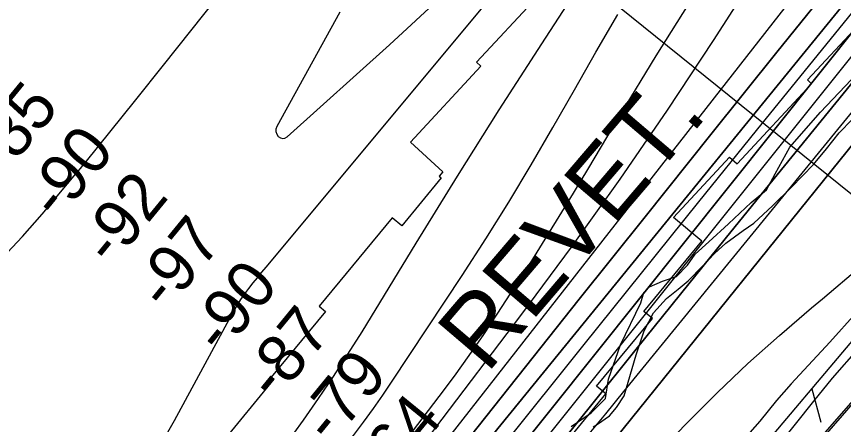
# Model space of a CAD drawing. Extents: x 3598634 to 3636690, y 517270 to 542944.
# Drawn here: x 3606411 to 3607580, y 527991 to 528569 of the extents above; entities that cross this region are included whole.
import ezdxf

# ---------------------------------------------------------------- set-up
doc = ezdxf.new("R2010")
doc.units = 0
for name, color, linetype in [('V-FLOD-BASE', 7, 'Continuous'), ('V-LEVE-TOET', 7, 'Continuous'), ('V-RIVR-EDGE', 7, 'Continuous'), ('V-RIVR-RANG', 7, 'Continuous'), ('V-RRAP-FSHR', 7, 'Continuous'), ('V-RRAP-RVMT', 7, 'Continuous'), ('V-RRAP-RVMT-IDEN', 7, 'Continuous'), ('V-SITE-VEGE', 7, 'Continuous'), ('V-SURV-LINE', 7, 'Continuous'), ('V-TOPO-DPTH', 7, 'Continuous'), ('V-TOPO-MAJR', 7, 'Continuous'), ('V-TOPO-MINR', 7, 'Continuous'), ('V-TOPO-WATR', 7, 'Continuous')]:
    doc.layers.add(name, color=color, linetype=linetype)

msp = doc.modelspace()

# ---------------------------------------------------------------- linework, layer by layer
at = {"layer": 'V-FLOD-BASE'}
msp.add_lwpolyline([(3606855.7, 527176), (3606941.6, 527272.6), (3607017.1, 527362.2), (3607123.3, 527485.2), (3607190.4, 527557.4), (3607286.8, 527667.9), (3607388.8, 527786.7), (3607446.1, 527850.6), (3607578.9, 528003.5), (3607669.7, 528108.4), (3607782.2, 528239), (3607843.7, 528310.5), (3607962.5, 528439.8), (3608057.5, 528550.9), (3608164.4, 528673.2)], dxfattribs=at)
at = {"layer": 'V-LEVE-TOET'}
msp.add_lwpolyline([(3607601.5, 528098.8), (3607564.4, 528056.4), (3607537.9, 528023.8), (3607488.2, 527961.2), (3607419.1, 527881.3), (3607381.3, 527839), (3607353.4, 527805.6), (3607326.1, 527776.4), (3607292.6, 527739.6), (3607250.6, 527684.7), (3607177.3, 527602), (3607062, 527470.7), (3606981.7, 527383.2), (3606929.9, 527320), (3606868.4, 527249.1), (3606793, 527162.3)], dxfattribs=at)
at = {"layer": 'V-RIVR-EDGE'}
msp.add_lwpolyline([(3607195.5, 527988.1), (3607223.8, 528007.2), (3607243.7, 528027.6), (3607247.9, 528055.2), (3607264.9, 528103.7), (3607293.8, 528163.1), (3607298.1, 528177.5), (3607305.9, 528185.9), (3607324.5, 528193.7), (3607344.3, 528200.2), (3607360, 528216.4), (3607370.8, 528232), (3607390.1, 528249.3), (3607417.8, 528275.1), (3607449.7, 528305), (3607471.3, 528323), (3607484, 528345.7), (3607504.5, 528383.5), (3607547.8, 528433.2), (3607600.2, 528488.3)], dxfattribs=at)
at = {"layer": 'V-RIVR-RANG'}
msp.add_line((3607752.6, 528186.5), (3607037.5, 528765.2), dxfattribs=at)
at = {"layer": 'V-RRAP-FSHR'}
msp.add_line((3607535.7, 528041.1), (3607548.3, 527993.9), dxfattribs=at)
for points in [[(3605375.2, 525433.8), (3605456, 525580.5), (3605630.7, 525877.6), (3605746.8, 526080.3), (3605800.6, 526159), (3605867.3, 526231.6), (3605948.4, 526309.6), (3606191.9, 526556.5), (3606564.8, 526949.6), (3606877.9, 527278.9), (3607054.8, 527479.5), (3607380.2, 527856.8), (3607669.2, 528199.4), (3608066.5, 528645), (3608475.6, 529114.7), (3608696.8, 529377), (3608831.9, 529536), (3608922.8, 529648.8), (3609014.7, 529727.8), (3609124.2, 529832), (3609276.1, 529976.3)], [(3607360.2, 527833.6), (3607380.2, 527856.8), (3607669.2, 528199.4), (3607973.9, 528541.1)]]:
    msp.add_lwpolyline(points, dxfattribs=at)
at = {"layer": 'V-RRAP-RVMT'}
for p, q in [((3607166.6, 528617.3), (3607061.3, 528503.7)), ((3607529.4, 528478.8), (3607630.3, 528587.7)), ((3607067.4, 528498.1), (3606968, 528390.8)), ((3607061.3, 528503.7), (3607067.4, 528498.1)), ((3607430, 528359.7), (3607535.2, 528473.4)), ((3607535.2, 528473.4), (3607529.4, 528478.8)), ((3606968, 528390.8), (3607013.7, 528348.5)), ((3607339.9, 528283.9), (3607419.3, 528369.6)), ((3607419.3, 528369.6), (3607430, 528359.7)), ((3607013.7, 528348.5), (3607008.8, 528342.5)), ((3607008.8, 528342.5), (3607011.7, 528340)), ((3607011.7, 528340), (3606955.7, 528271.9)), ((3607380.3, 528250.6), (3607339.9, 528283.9)), ((3606942, 528283.4), (3606838.9, 528158.2)), ((3606955.7, 528271.9), (3606942, 528283.4)), ((3607298.3, 528150.9), (3607380.3, 528250.6)), ((3606838.9, 528158.2), (3606847.8, 528150.9)), ((3606847.8, 528150.9), (3606771, 528057.9)), ((3607310.2, 528141.1), (3607298.3, 528150.9)), ((3607231.3, 528045.2), (3607310.2, 528141.1)), ((3606774.7, 528054.9), (3606690.9, 527952.6)), ((3606771, 528057.9), (3606774.7, 528054.9)), ((3607244.4, 528034.4), (3607231.3, 528045.2)), ((3607167.8, 527941.3), (3607244.4, 528034.4))]:
    msp.add_line(p, q, dxfattribs=at)
at = {"layer": 'V-SITE-VEGE'}
for points in [[(3607226.4, 527987.7), (3607232.7, 527991.2), (3607249.5, 528003), (3607259.2, 528014.8), (3607270.4, 528031.5), (3607287.3, 528089.3), (3607298.6, 528123.4), (3607311.9, 528149.1), (3607330, 528169.2), (3607346.8, 528182.4), (3607360.7, 528194.2), (3607381.7, 528215.7), (3607397.8, 528233.1), (3607413.8, 528247.7), (3607438.3, 528265.7), (3607453.6, 528276.1), (3607480.1, 528300.4), (3607506.7, 528326.8), (3607538.1, 528358.8), (3607556.3, 528381), (3607574.5, 528403.9), (3607592.6, 528422.7)], [(3607598.1, 528149), (3607561.1, 528107.3), (3607506.6, 528048.2), (3607485.6, 528024.6), (3607461.9, 527995.4), (3607437.4, 527967.6)]]:
    msp.add_lwpolyline(points, dxfattribs=at)
at = {"layer": 'V-SURV-LINE'}
msp.add_lwpolyline([(3606955.7, 527293.4), (3607820.1, 528283.5)], dxfattribs=at)
at = {"layer": 'V-TOPO-DPTH'}
for points in [[(3606235.2, 526930.9), (3606440.2, 527167.6), (3606463.9, 527195.4), (3606487.4, 527223.4), (3606510.5, 527251.7), (3606533.4, 527280.2), (3607009.7, 527882.8), (3607014, 527888.2), (3607018.2, 527893.6), (3607022.4, 527899), (3607026.7, 527904.4), (3607030.2, 527908.9), (3607032.6, 527912.1), (3607035.1, 527915.2), (3607037.6, 527918.3), (3607040.1, 527921.5), (3607042.6, 527924.6), (3607045.1, 527927.7), (3607047.6, 527930.8), (3607050.1, 527933.9), (3607754.7, 528800.4)], [(3607754.7, 528800.4), (3607050.1, 527933.9), (3607047.6, 527930.8), (3607045.1, 527927.7), (3607042.6, 527924.6), (3607040.1, 527921.5), (3607037.6, 527918.3), (3607035.1, 527915.2), (3607032.6, 527912.1), (3607030.2, 527908.9), (3607026.7, 527904.4), (3607022.4, 527899), (3607018.2, 527893.6), (3607014, 527888.2), (3607009.7, 527882.8), (3606533.4, 527280.2), (3606510.5, 527251.7), (3606487.4, 527223.4), (3606463.9, 527195.4), (3606440.2, 527167.6), (3606235.2, 526930.9)], [(3607814.4, 528747.3), (3607476.4, 528331.4), (3607413.2, 528253.5), (3607350.1, 528175.5), (3607287.2, 528097.4), (3607224.4, 528019.3), (3607109.4, 527875.9), (3607104.1, 527869.4), (3607098.9, 527862.8), (3607093.6, 527856.2), (3607088.4, 527849.7), (3607032.3, 527779.2), (3606999, 527737.5), (3606965.8, 527695.7), (3606932.5, 527653.9), (3606899.2, 527612.2), (3606584.6, 527217.9), (3606568.4, 527197.7), (3606552.1, 527177.6), (3606535.6, 527157.7), (3606519.1, 527137.7), (3606362.9, 526951.2)], [(3606362.9, 526951.2), (3606519.1, 527137.7), (3606535.6, 527157.7), (3606552.1, 527177.6), (3606568.4, 527197.7), (3606584.6, 527217.9), (3606899.2, 527612.2), (3606932.5, 527653.9), (3606965.8, 527695.7), (3606999, 527737.5), (3607032.3, 527779.2), (3607088.4, 527849.7), (3607093.6, 527856.2), (3607098.9, 527862.8), (3607104.1, 527869.4), (3607109.4, 527875.9), (3607224.4, 528019.3), (3607287.2, 528097.4), (3607350.1, 528175.5), (3607413.2, 528253.5), (3607476.4, 528331.4), (3607814.4, 528747.3)], [(3606352.7, 527134.1), (3606433, 527226.8), (3606442.3, 527237.7), (3606451.5, 527248.7), (3606460.6, 527259.8), (3606469.6, 527270.9), (3606564.2, 527390), (3606620.4, 527460.9), (3606676.5, 527531.8), (3606732.4, 527602.8), (3606788.3, 527673.8), (3606965.9, 527900.3), (3606983, 527922.1), (3607000.1, 527944), (3607017.2, 527965.8), (3607034.2, 527987.6), (3607564, 528666.3)], [(3606352.7, 527134.1), (3606433, 527226.8), (3606442.3, 527237.7), (3606451.5, 527248.7), (3606460.6, 527259.8), (3606469.6, 527270.9), (3606564.2, 527390), (3606620.4, 527460.9), (3606676.5, 527531.8), (3606732.4, 527602.8), (3606788.3, 527673.8), (3606965.9, 527900.3), (3606983, 527922.1), (3607000.1, 527944), (3607017.2, 527965.8), (3607034.2, 527987.6), (3607564, 528666.3)], [(3606294, 527032.6), (3606436.6, 527197.3), (3606453.1, 527216.6), (3606469.4, 527236.1), (3606485.5, 527255.7), (3606501.4, 527275.5), (3606780.9, 527628.5), (3606820.5, 527678.5), (3606860.1, 527728.7), (3606899.5, 527778.9), (3606938.8, 527829.1), (3607003.9, 527912.3), (3607010.7, 527921), (3607017.5, 527929.7), (3607024.4, 527938.3), (3607031.2, 527947), (3607206.8, 528168.1), (3607299.8, 528284.9), (3607392.9, 528401.6), (3607486.3, 528518.1), (3607579.8, 528634.5)], [(3607579.8, 528634.5), (3607486.3, 528518.1), (3607392.9, 528401.6), (3607299.8, 528284.9), (3607206.8, 528168.1), (3607031.2, 527947), (3607024.4, 527938.3), (3607017.5, 527929.7), (3607010.7, 527921), (3607003.9, 527912.3), (3606938.8, 527829.1), (3606899.5, 527778.9), (3606860.1, 527728.7), (3606820.5, 527678.5), (3606780.9, 527628.5), (3606501.4, 527275.5), (3606485.5, 527255.7), (3606469.4, 527236.1), (3606453.1, 527216.6), (3606436.6, 527197.3), (3606294, 527032.6)], [(3607764.9, 528600.3), (3607732.3, 528559.8), (3607699.6, 528519.3), (3607166.6, 527857.8), (3607154.3, 527842.6), (3607141.9, 527827.4), (3607129.4, 527812.4), (3607116.9, 527797.4), (3606811.9, 527434.6), (3606773.3, 527388.5), (3606734.8, 527342.3), (3606696.5, 527295.9), (3606658.4, 527249.4), (3606638.3, 527224.8), (3606610.2, 527190.6), (3606582.1, 527156.4), (3606553.9, 527122.4), (3606525.5, 527088.4), (3606200.6, 526699.9)], [(3607641.8, 528607.4), (3607607, 528563.8), (3607103.4, 527932.6), (3607085.7, 527910.4), (3607068, 527888.2), (3607050.3, 527865.9), (3607032.7, 527843.7), (3606691, 527412), (3606662.8, 527376.5), (3606634.7, 527340.9), (3606606.5, 527305.4), (3606578.3, 527269.9), (3606531, 527210.3), (3606526.4, 527204.6), (3606521.8, 527199), (3606517.2, 527193.3), (3606512.6, 527187.7), (3606479.5, 527148.3), (3606458.2, 527123.1), (3606436.6, 527098), (3606414.8, 527073.2), (3606392.8, 527048.6)], [(3606392.8, 527048.6), (3606414.8, 527073.2), (3606436.6, 527098), (3606458.2, 527123.1), (3606479.5, 527148.3), (3606512.6, 527187.7), (3606517.2, 527193.3), (3606521.8, 527199), (3606526.4, 527204.6), (3606531, 527210.3), (3606578.3, 527269.9), (3606606.5, 527305.4), (3606634.7, 527340.9), (3606662.8, 527376.5), (3606691, 527412), (3607032.7, 527843.7), (3607050.3, 527865.9), (3607068, 527888.2), (3607085.7, 527910.4), (3607103.4, 527932.6), (3607607, 528563.8), (3607641.8, 528607.4)]]:
    msp.add_lwpolyline(points, dxfattribs=at)
at = {"layer": 'V-TOPO-MAJR'}
for points in [[(3606405.6, 527229), (3606411.1, 527235.3), (3606429.4, 527256.3), (3606431.5, 527258.8), (3606433.6, 527261.3), (3606435.6, 527263.8), (3606437.7, 527266.3), (3606459.8, 527294), (3606472.8, 527310.5), (3606485.9, 527326.9), (3606498.9, 527343.3), (3606511.9, 527359.8), (3606962.4, 527932.5), (3606972.5, 527945.4), (3606982.5, 527958.4), (3606992.5, 527971.4), (3607002.5, 527984.5), (3607125.5, 528146.9), (3607195.9, 528242), (3607264.7, 528338.1), (3607331.3, 528435.8), (3607396.5, 528534.5), (3607595.7, 528844.2)], [(3606868.3, 528574.7), (3606779.1, 528413), (3606777.9, 528409.2), (3606777.7, 528405.5), (3606778.9, 528402), (3606781, 528398.6), (3606784.2, 528396.7), (3606787.4, 528395.8), (3606790.6, 528396.5), (3606793.9, 528398.2), (3606938.5, 528528.4), (3607012.8, 528597.7)]]:
    msp.add_lwpolyline(points, dxfattribs=at)
at = {"layer": 'V-TOPO-MINR'}
for points in [[(3606390.7, 528226.3), (3606419.4, 528257.1), (3606447.3, 528288.8), (3606495, 528345.6), (3606498.3, 528349.6), (3606501.6, 528353.5), (3606504.9, 528357.5), (3606508.1, 528361.5), (3606579.8, 528450.8), (3606618.8, 528499.6), (3606657.6, 528548.4), (3606696.1, 528597.5), (3606734.6, 528646.6), (3607212.9, 529261.6), (3607227, 529280), (3607240.9, 529298.4), (3607254.6, 529317), (3607268.2, 529335.8), (3607599.5, 529800), (3607644.1, 529862.4), (3607688.7, 529924.8)], [(3608167.6, 529919.3), (3608117.8, 529858.1), (3608068, 529796.9), (3608018.1, 529735.6), (3607540, 529148.3), (3607517.1, 529120.3), (3607494.1, 529092.3), (3607471, 529064.4), (3607447.9, 529036.5), (3606763.5, 528213.8), (3606757.3, 528206.3), (3606751.2, 528198.7), (3606745.1, 528191.2), (3606739.1, 528183.5), (3606733.3, 528175.7), (3606727.8, 528167.8), (3606722.7, 528159.5), (3606717.8, 528151.1), (3606633.9, 527995.8), (3606585.3, 527910.9), (3606534, 527827.8), (3606478.6, 527747.4), (3606420.5, 527668.7), (3606248.6, 527447.8)], [(3606207.9, 526878.1), (3606462.1, 527163.5), (3606483.2, 527187.4), (3606504.1, 527211.6), (3606524.7, 527235.9), (3606545.2, 527260.4), (3606565.4, 527285.1), (3606585.6, 527309.9), (3606605.5, 527334.9), (3606625.3, 527359.9), (3607003.7, 527840.4), (3607027.7, 527870.9), (3607051.9, 527901.4), (3607076.1, 527931.8), (3607100.3, 527962.2), (3607213.7, 528103.9), (3607294.8, 528205.1), (3607376, 528306.1), (3607457.4, 528407), (3607538.9, 528507.8), (3607788.1, 528815.6)], [(3606235.2, 526930.9), (3606440.2, 527167.6), (3606463.9, 527195.4), (3606487.4, 527223.4), (3606510.5, 527251.7), (3606533.4, 527280.2), (3607009.7, 527882.8), (3607014, 527888.2), (3607018.2, 527893.6), (3607022.4, 527899), (3607026.7, 527904.4), (3607030.2, 527908.9), (3607032.6, 527912.1), (3607035.1, 527915.2), (3607037.6, 527918.3), (3607040.1, 527921.5), (3607042.6, 527924.6), (3607045.1, 527927.7), (3607047.6, 527930.8), (3607050.1, 527933.9), (3607754.7, 528800.4)], [(3606284.8, 526829.2), (3606522.3, 527112.8), (3606544.8, 527139.8), (3606567.2, 527167), (3606589.4, 527194.2), (3606611.5, 527221.6), (3607005.2, 527711.9), (3607023.5, 527734.8), (3607042, 527757.7), (3607060.4, 527780.5), (3607078.9, 527803.3), (3607097.4, 527826), (3607115.9, 527848.8), (3607134.5, 527871.5), (3607153, 527894.3), (3607167.3, 527911.7), (3607193, 527943.1), (3607218.6, 527974.5), (3607244.3, 528006), (3607269.9, 528037.4), (3607833.2, 528728.4)], [(3606352.7, 527134.1), (3606433, 527226.8), (3606442.3, 527237.7), (3606451.5, 527248.7), (3606460.6, 527259.8), (3606469.6, 527270.9), (3606564.2, 527390), (3606620.4, 527460.9), (3606676.5, 527531.8), (3606732.4, 527602.8), (3606788.3, 527673.8), (3606965.9, 527900.3), (3606983, 527922.1), (3607000.1, 527944), (3607017.2, 527965.8), (3607034.2, 527987.6), (3607564, 528666.3)], [(3606294, 527032.6), (3606436.6, 527197.3), (3606453.1, 527216.6), (3606469.4, 527236.1), (3606485.5, 527255.7), (3606501.4, 527275.5), (3606780.9, 527628.5), (3606820.5, 527678.5), (3606860.1, 527728.7), (3606899.5, 527778.9), (3606938.8, 527829.1), (3607003.9, 527912.3), (3607010.7, 527921), (3607017.5, 527929.7), (3607024.4, 527938.3), (3607031.2, 527947), (3607206.8, 528168.1), (3607299.8, 528284.9), (3607392.9, 528401.6), (3607486.3, 528518.1), (3607579.8, 528634.5)], [(3606299.3, 527384.5), (3606681.2, 527823.8), (3606712.9, 527861.3), (3606743.9, 527899.4), (3606773.9, 527938.4), (3606803.1, 527977.9), (3606816.6, 527996.8), (3606838.2, 528027.6), (3606859.2, 528058.7), (3606879.6, 528090.2), (3606899.6, 528122), (3606976.3, 528247.7), (3607034.6, 528342.3), (3607093.6, 528436.5), (3607153.6, 528530.1), (3607214.1, 528623.3)], [(3606200.6, 526699.9), (3606525.5, 527088.4), (3606553.9, 527122.4), (3606582.1, 527156.4), (3606610.2, 527190.6), (3606638.3, 527224.8), (3606658.4, 527249.4), (3606696.5, 527295.9), (3606734.8, 527342.3), (3606773.3, 527388.5), (3606811.9, 527434.6), (3607116.9, 527797.4), (3607129.4, 527812.4), (3607141.9, 527827.4), (3607154.3, 527842.6), (3607166.6, 527857.8), (3607699.6, 528519.3), (3607732.3, 528559.8), (3607764.9, 528600.3)], [(3606392.8, 527048.6), (3606414.8, 527073.2), (3606436.6, 527098), (3606458.2, 527123.1), (3606479.5, 527148.3), (3606512.6, 527187.7), (3606517.2, 527193.3), (3606521.8, 527199), (3606526.4, 527204.6), (3606531, 527210.3), (3606578.3, 527269.9), (3606606.5, 527305.4), (3606634.7, 527340.9), (3606662.8, 527376.5), (3606691, 527412), (3607032.7, 527843.7), (3607050.3, 527865.9), (3607068, 527888.2), (3607085.7, 527910.4), (3607103.4, 527932.6), (3607607, 528563.8), (3607641.8, 528607.4)], [(3606387.4, 527010.3), (3606431.6, 527062.2), (3606515.8, 527162.7), (3606526.4, 527175.5), (3606536.9, 527188.3), (3606547.4, 527201.2), (3606557.8, 527214.1), (3606667.4, 527351.9), (3606732.6, 527433.8), (3606797.7, 527515.7), (3606862.8, 527597.6), (3606927.9, 527679.5), (3607060.7, 527846.7), (3607072.1, 527861.1), (3607083.5, 527875.4), (3607094.9, 527889.8), (3607106.4, 527904.1), (3607573.8, 528489.3), (3607616.8, 528543), (3607659.9, 528596.7)], [(3606971.1, 527980.8), (3607008.6, 528030.3), (3607030.1, 528059.3), (3607051.2, 528088.6), (3607071.6, 528118.4), (3607091.6, 528148.4), (3607109, 528175.2), (3607137.1, 528219), (3607164.9, 528263), (3607192.1, 528307.4), (3607218.9, 528352.1), (3607264.9, 528429.7), (3607315.3, 528512.7), (3607366.9, 528595)], [(3606365.7, 527325.1), (3606457, 527431.8), (3606506.4, 527490.5), (3606555.3, 527549.6), (3606603.3, 527609.5), (3606650.7, 527669.8), (3606887.6, 527975.4), (3606901.8, 527994.2), (3606915.7, 528013.2), (3606929.2, 528032.5), (3606942.4, 528052.1), (3607041.2, 528202), (3607074.5, 528253.7), (3607107, 528305.7), (3607138.6, 528358.4), (3607169.4, 528411.5), (3607199.9, 528464.8), (3607230.4, 528518.2), (3607261.1, 528571.4)], [(3607328.1, 527960.8), (3607359.9, 527993.7), (3607402.1, 528035.9), (3607445.3, 528077.1), (3607489.7, 528117), (3607535.1, 528155.8), (3607550.7, 528168.7), (3607603.8, 528214.1)]]:
    msp.add_lwpolyline(points, dxfattribs=at)
at = {"layer": 'V-TOPO-WATR'}
msp.add_lwpolyline([(3606362.9, 526951.2), (3606519.1, 527137.7), (3606535.6, 527157.7), (3606552.1, 527177.6), (3606568.4, 527197.7), (3606584.6, 527217.9), (3606899.2, 527612.2), (3606932.5, 527653.9), (3606965.8, 527695.7), (3606999, 527737.5), (3607032.3, 527779.2), (3607088.4, 527849.7), (3607093.6, 527856.2), (3607098.9, 527862.8), (3607104.1, 527869.4), (3607109.4, 527875.9), (3607224.4, 528019.3), (3607287.2, 528097.4), (3607350.1, 528175.5), (3607413.2, 528253.5), (3607476.4, 528331.4), (3607814.4, 528747.3)], dxfattribs=at)

# ---------------------------------------------------------------- texts
at = {"layer": 'V-RIVR-RANG'}
for s, p in [('-85', (3606391.1, 528339.6)), ('-90', (3606469.6, 528277.6)), ('-92', (3606545.7, 528212.6)), ('-97', (3606622.9, 528149.2)), ('-90', (3606701.4, 528087.1)), ('-87', (3606776.8, 528021.4)), ('-79', (3606856.2, 527960.6)), ('-64', (3606933.8, 527897.5))]:
    msp.add_text(s, height=67, rotation=50.7334, dxfattribs=at).set_placement(p)
at = {"layer": 'V-RRAP-RVMT-IDEN'}
msp.add_text('REVET.', height=100, rotation=49.531, dxfattribs=at).set_placement((3607076, 528061.5))

doc.saveas('drawing.dxf')
